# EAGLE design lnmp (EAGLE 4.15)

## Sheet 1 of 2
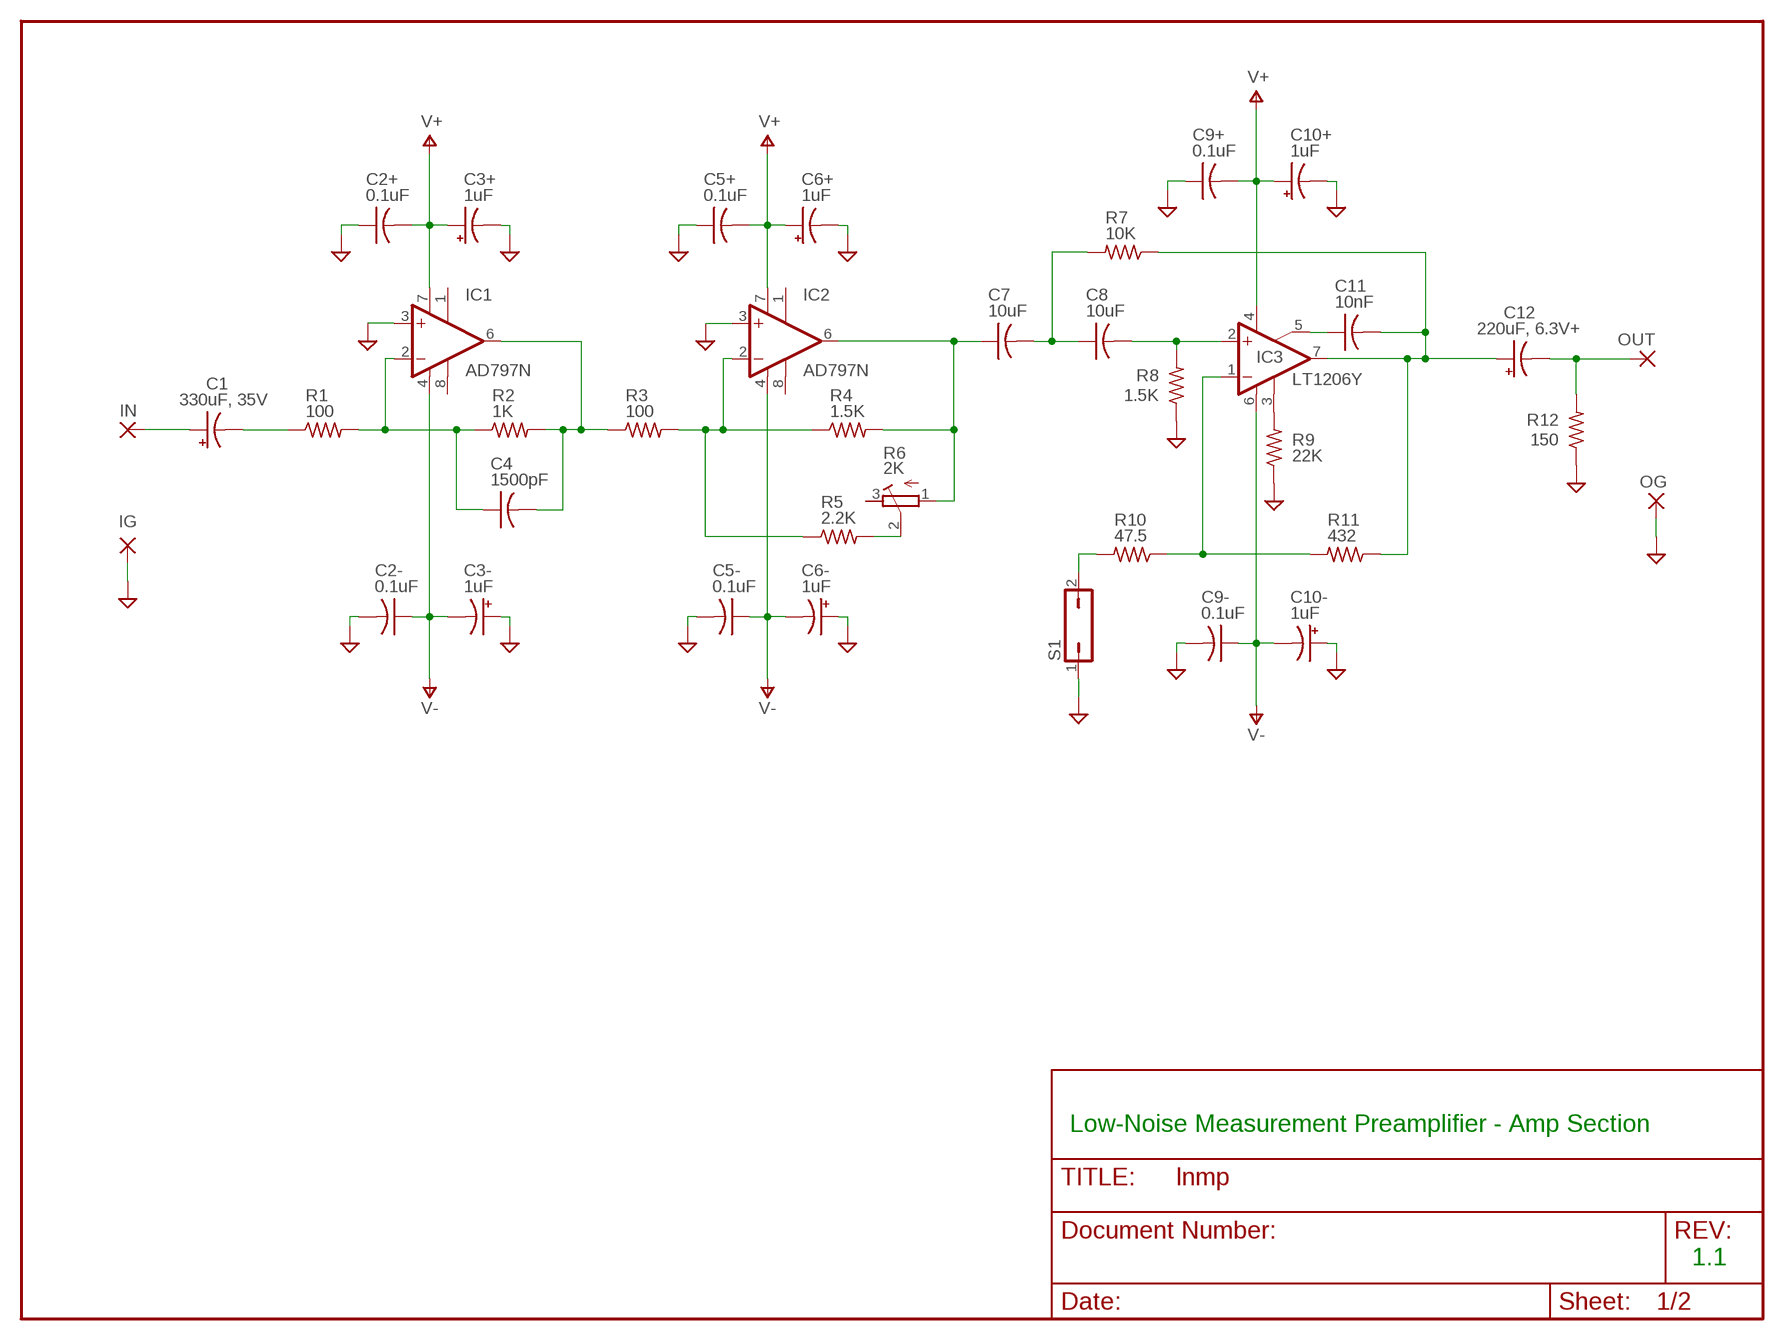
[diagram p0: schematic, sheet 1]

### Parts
C1  330uF, 35V  CPOL-USE5-10.5  [E5-10,5]
C2+  0.1uF  C-US050-025X075  [C050-025X075]
C2-  0.1uF  C-US050-025X075  [C050-025X075]
C3+  1uF  CPOL-USE2-4  [E2-4]
C3-  1uF  CPOL-USE2-4  [E2-4]
C4  1500pF  C-US050-025X075  [C050-025X075]
C5+  0.1uF  C-US050-025X075  [C050-025X075]
C5-  0.1uF  C-US050-025X075  [C050-025X075]
C6+  1uF  CPOL-USE2-4  [E2-4]
C6-  1uF  CPOL-USE2-4  [E2-4]
C7  10uF  C-US050-075X075  [C050-075X075]
C8  10uF  C-US050-075X075  [C050-075X075]
C9+  0.1uF  C-US050-025X075  [C050-025X075]
C9-  0.1uF  C-US050-025X075  [C050-025X075]
C10+  1uF  CPOL-USE2-4  [E2-4]
C10-  1uF  CPOL-USE2-4  [E2-4]
C11  10nF  C-US050-025X075  [C050-025X075]
C12  220uF, 6.3V+  CPOL-USE3.5-8  [E3,5-8]
IC1  AD797N  OPA132P  [DIL08]
IC2  AD797N  OPA132P  [DIL08]
IC3  LT1206Y  [TO-220-7]
IG  2,15/1,0  [2,15/1,0]
IN  2,15/1,0  [2,15/1,0]
OG  2,15/1,0  [2,15/1,0]
OUT  2,15/1,0  [2,15/1,0]
R1  100  R-US_0207/10  [0207/10]
R2  1K  R-US_0207/10  [0207/10]
R3  100  R-US_0207/10  [0207/10]
R4  1.5K  R-US_0207/10  [0207/10]
R5  2.2K  R-US_0207/10  [0207/10]
R6  2K  R-TRIMM3296W  [RTRIM3296W]
R7  10K  R-US_0207/10  [0207/10]
R8  1.5K  R-US_0207/10  [0207/10]
R9  22K  R-US_0207/10  [0207/10]
R10  47.5  R-US_0207/10  [0207/10]
R11  432  R-US_0207/10  [0207/10]
R12  150  R-US_0207/10  [0207/10]
S1  JP1Q  [JP1]

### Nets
GND1: C2+.1 C2-.2 C3+.- C3-.+ C5+.1 C5-.2 C6+.- C6-.+ C9+.1 C9-.2 C10+.- C10-.+ IC1.3(+IN) IC2.3(+IN) IG.1(P) OG.1(P) R8.1 R9.1 R12.1 S1.1 ; also sheet 2
N$1: C7.2 C8.1 R7.2
N$2: C8.2 IC3.2(+IN) R8.2
N$3: C4.1 IC1.2(-IN) R1.2 R2.1
N$5: C1.+ IN.1(P)
N$7: C11.2 C12.+ IC3.7(OUT) R7.1 R11.1
N$8: C4.2 IC1.6(OUT) R2.2 R3.1
N$9: C1.- R1.1
N$11: R5.2 R6.2(S)
N$12: IC2.2(-IN) R3.2 R4.1 R5.1
N$13: IC3.1(-IN) R10.1 R11.2
N$14: C7.1 IC2.6(OUT) R4.2 R6.1(E)
N$15: IC3.3(SD) R9.2
N$16: C11.1 IC3.5(COMP)
N$17: R10.2 S1.2
OUT: C12.- OUT.1(P) R12.2
V+: C2+.2 C3+.+ C5+.2 C6+.+ C9+.2 C10+.+ IC1.7(V+) IC2.7(V+) IC3.4(V+) ; also sheet 2
V-: C2-.1 C3-.- C5-.1 C6-.- C9-.1 C10-.- IC1.4(V-) IC2.4(V-) IC3.6(V-) ; also sheet 2
Unconnected: IC1.1(TRIM1) IC1.8(TRIM2) IC2.1(TRIM1) IC2.8(TRIM2) R6.3(A)

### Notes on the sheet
- Low-Noise Measurement Preamplifier - Amp Section
- 1.1

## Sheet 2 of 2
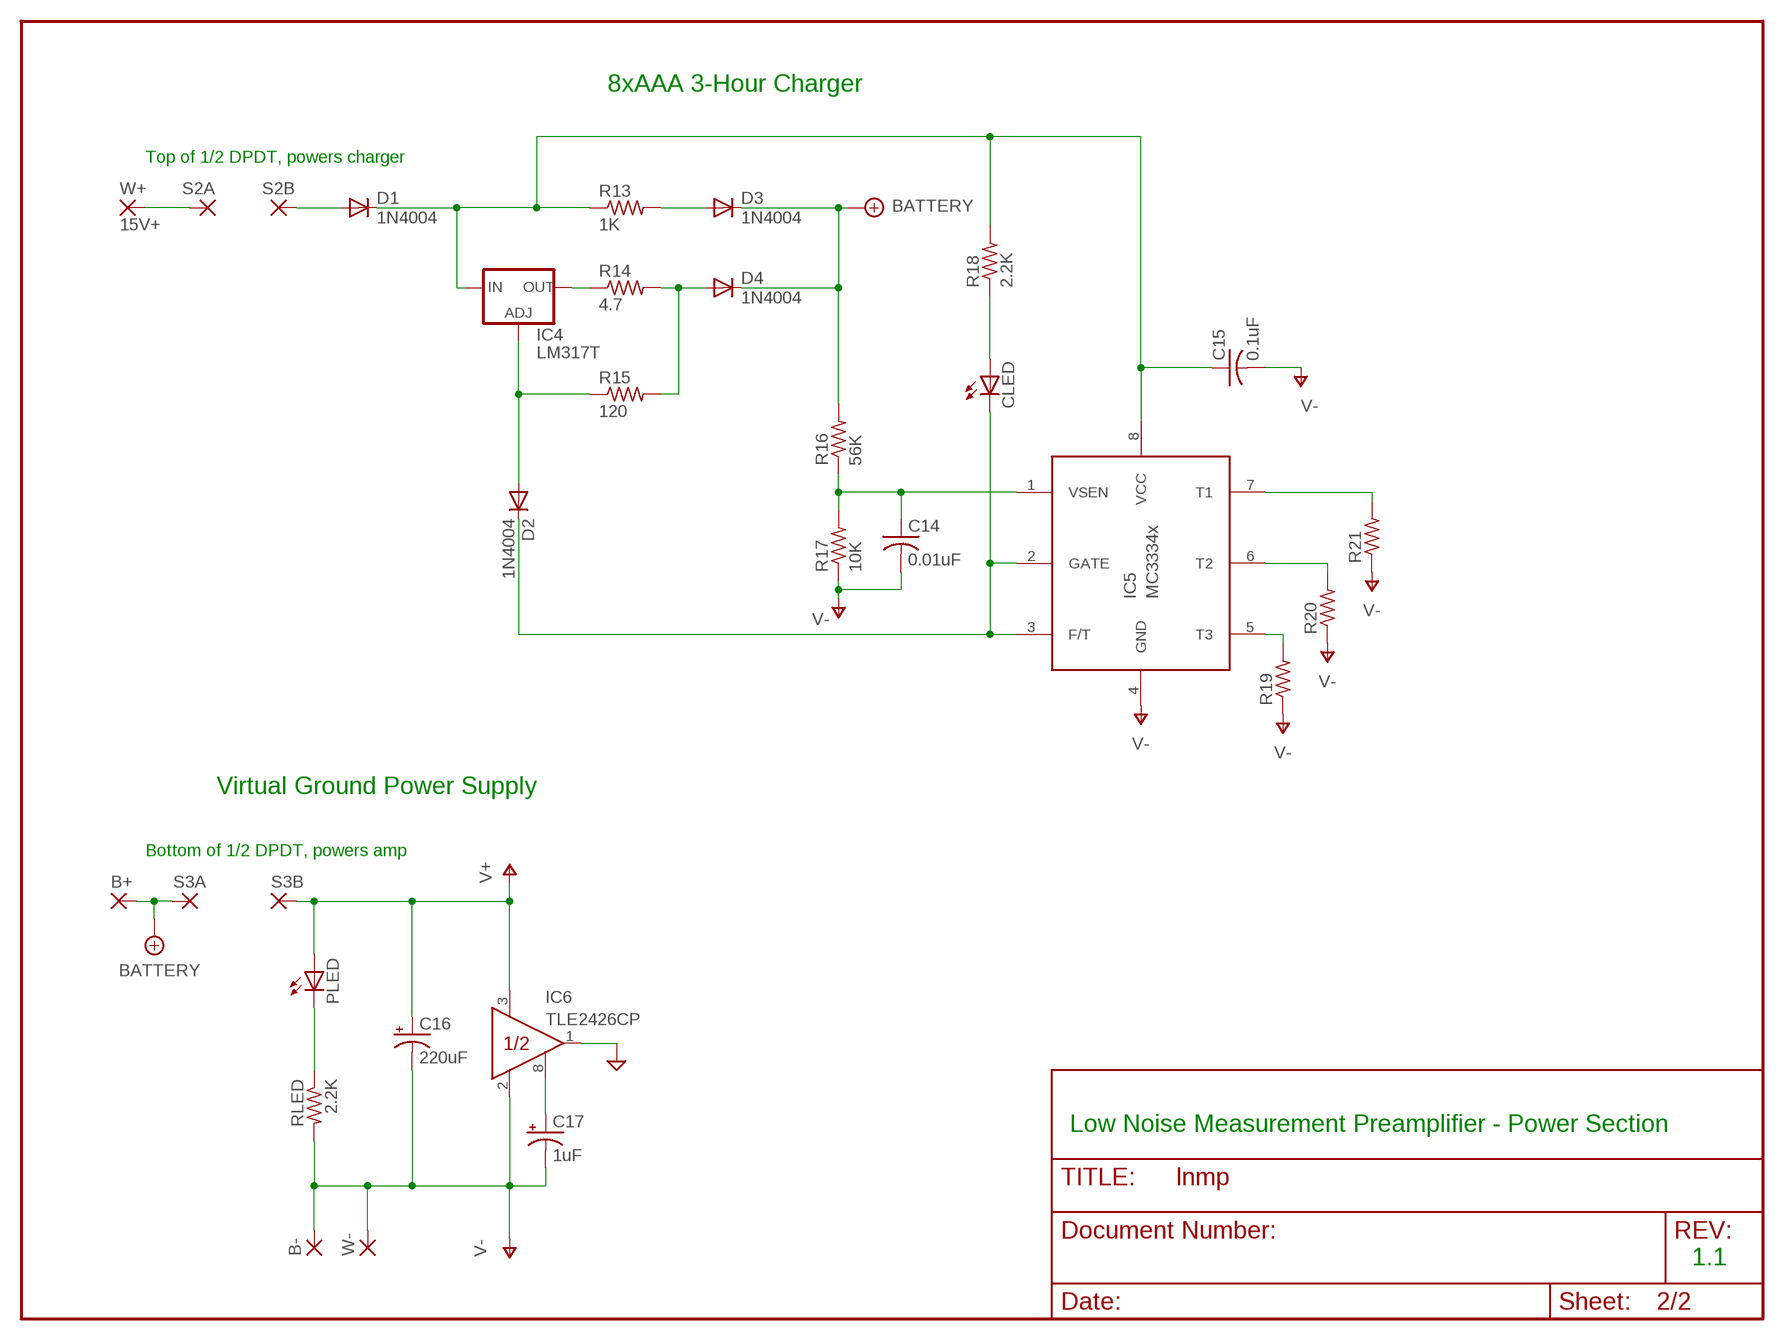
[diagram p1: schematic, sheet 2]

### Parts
B+  2,54/1,0  [2,54/1,0]
B-  2,15/1,0  [2,15/1,0]
C14  0.01uF  C-US050-025X075  [C050-025X075]
C15  0.1uF  C-US050-025X075  [C050-025X075]
C16  220uF  CPOL-USE5-10.5  [E5-10,5]
C17  1uF  CPOL-USE2-4  [E2-4]
CLED  LED3MM  [LED3MM]
D1  1N4004  [DO41-10]
D2  1N4004  [DO41-10]
D3  1N4004  [DO41-10]
D4  1N4004  [DO41-10]
IC4  LM317T  LM317TS  [317TS]
IC5  MC3334x  MC3334XP  [DIP-8]
IC6  TLE2426CP  [DIP-8]
PLED  LED3MM  [LED3MM]
R13  1K  R-US_0207/10  [0207/10]
R14  4.7  R-US_0411/15  [0411/15]
R15  120  R-US_0207/10  [0207/10]
R16  56K  R-US_0207/10  [0207/10]
R17  10K  R-US_0207/10  [0207/10]
R18  2.2K  R-US_0207/10  [0207/10]
R19  R-US_0207/10  [0207/10]
R20  R-US_0207/10  [0207/10]
R21  R-US_0207/10  [0207/10]
RLED  2.2K  R-US_0207/10  [0207/10]
S2A  2,54/1,0  [2,54/1,0]
S2B  2,54/1,0  [2,54/1,0]
S3A  2,54/1,0  [2,54/1,0]
S3B  2,54/1,0  [2,54/1,0]
W+  15V+  2,54/1,0  [2,54/1,0]
W-  2,54/1,0  [2,54/1,0]

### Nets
+10V: B+.1(P) D3.C D4.C R16.2 S3A.1(P) ; supply symbol labelled BATTERY
GND1: IC6.1(OUT) ; also sheet 1
N$4: C17.+ IC6.8(NR)
N$6: PLED.K(C) RLED.1
N$19: S2A.1(P) W+.1(P)
N$20: D1.A S2B.1(P)
N$22: IC4.2(OUT) R14.1
N$23: D4.A R14.2 R15.2
N$24: CLED.A R18.1
N$25: D2.A IC4.1(ADJ) R15.1
N$26: CLED.K(C) D2.C IC5.2(GATE) IC5.3(F/T)
N$27: C14.1 IC5.1(VSEN) R16.1 R17.2
N$28: C15.1 D1.C IC4.3(IN) IC5.8(VCC) R13.1 R18.2
N$29: IC5.5(T3) R19.2
N$30: D3.A R13.2
N$32: IC5.6(T2) R20.2
N$33: IC5.7(T1) R21.2
V+: C16.+ IC6.3(IN) PLED.A S3B.1(P) ; also sheet 1
V-: B-.1(P) C14.2 C15.2 C16.- C17.- IC5.4(GND) IC6.2(COM) R17.1 R19.1 R20.1 R21.1 RLED.2 W-.1(P) ; also sheet 1

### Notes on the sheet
- 8xAAA 3-Hour Charger
- Top of 1/2 DPDT, powers charger
- Virtual Ground Power Supply
- Bottom of 1/2 DPDT, powers amp
- Low Noise Measurement Preamplifier - Power Section
- 1.1

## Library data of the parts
B+ S2A S2B S3A S3B W+ W- = wirepad:2,54/1,0: THROUGH-HOLE PAD
B- IG IN OG OUT = wirepad:2,15/1,0: THROUGH-HOLE PAD
C1 C3+ C3- C6+ C6- C10+ C10- C12 C16 C17 = rcl:CPOL-US: POLARIZED CAPACITOR, American symbol
C2+ C2- C4 C5+ C5- C7 C8 C9+ C9- C11 C14 C15 = rcl:C-US: CAPACITOR, American symbol
CLED PLED = led:LED: LED
D1-D4 = diode:1N4004: DIODE
IC1 IC2 = burr-brown:OPA132: Operational Amplifiers High Speed FET-Input
IC3 = opamps:LT1206: Linear Technology LT1206 CFB op-amp with shutdown
IC4 = v-reg:LM317TS: VOLTAGE REGULATOR
IC5 = power-mgmt:MC3334X: Motorola MC3334x NiMH/NiCd fast charge controller
IC6 = tle2426:TLE2426*: Texas Instruments "rail splitter" with noise-reduction
R1-R5 R7-R21 RLED = rcl:R-US_: RESISTOR, American symbol
R6 = rcl:R-TRIMM: Trimm resistor
S1 = jumper:JP1Q: JUMPER

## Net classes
0 default: width 0.61 mm

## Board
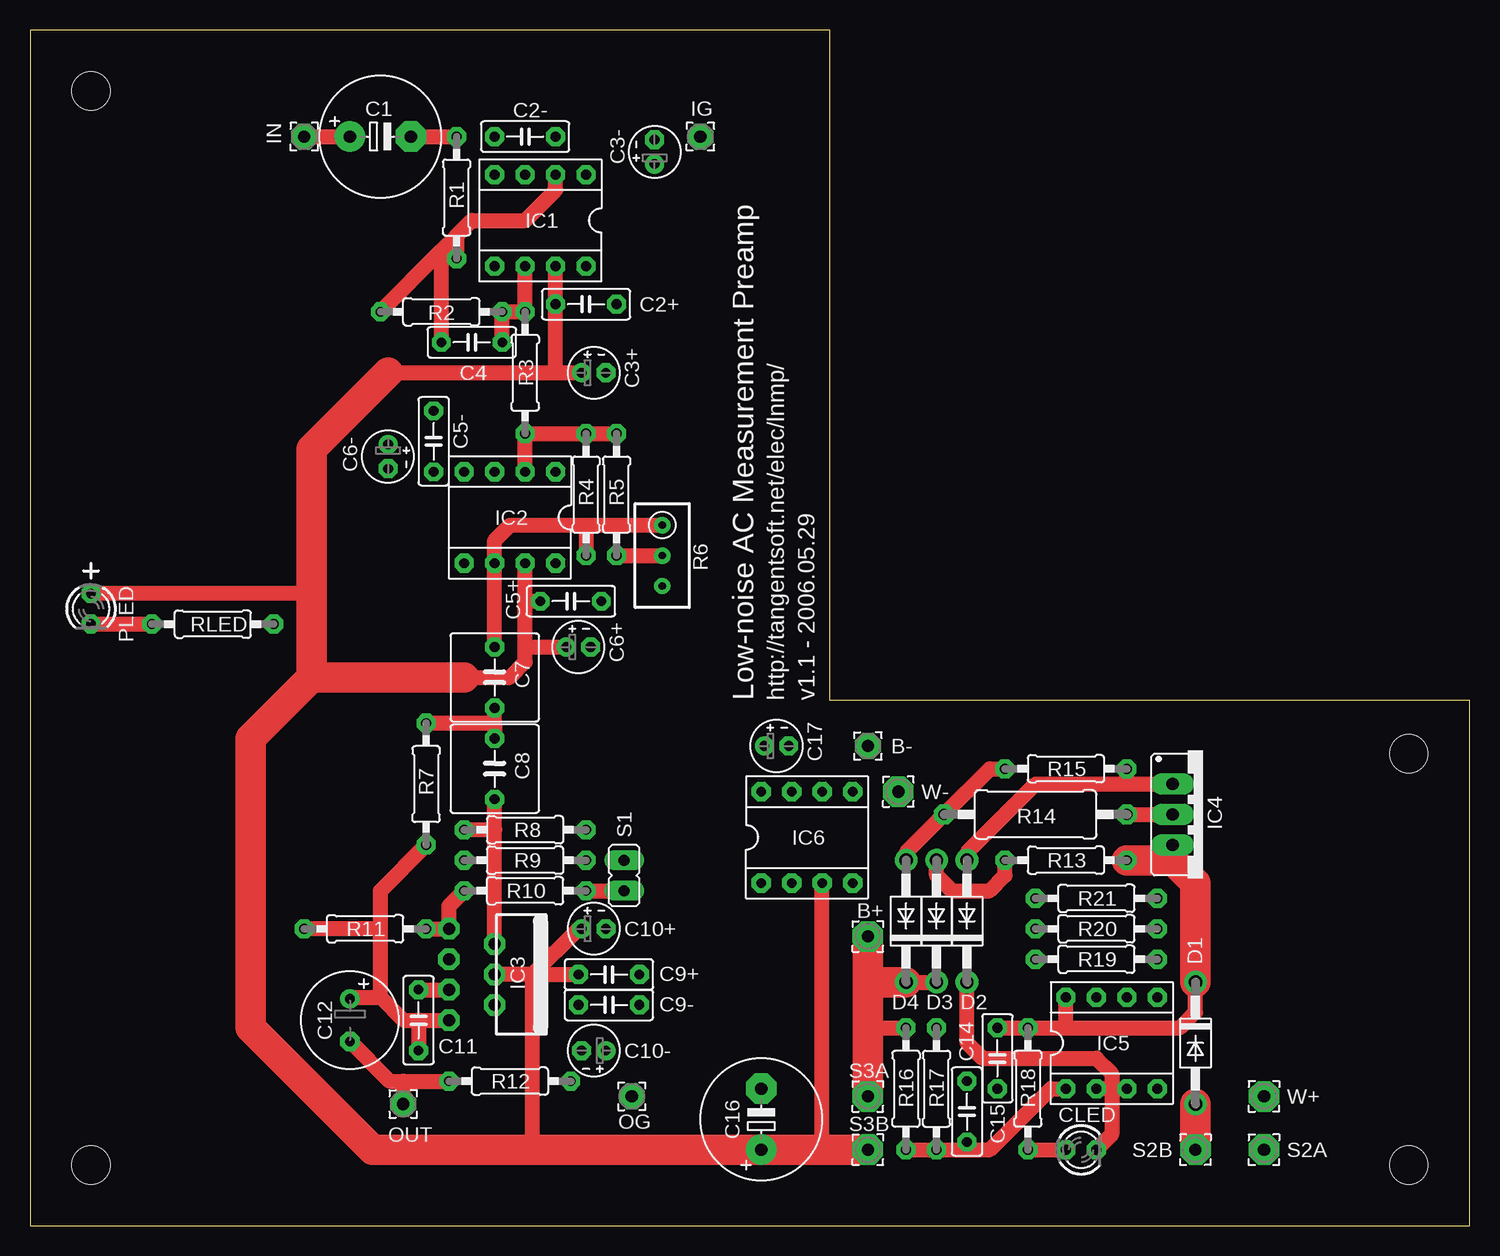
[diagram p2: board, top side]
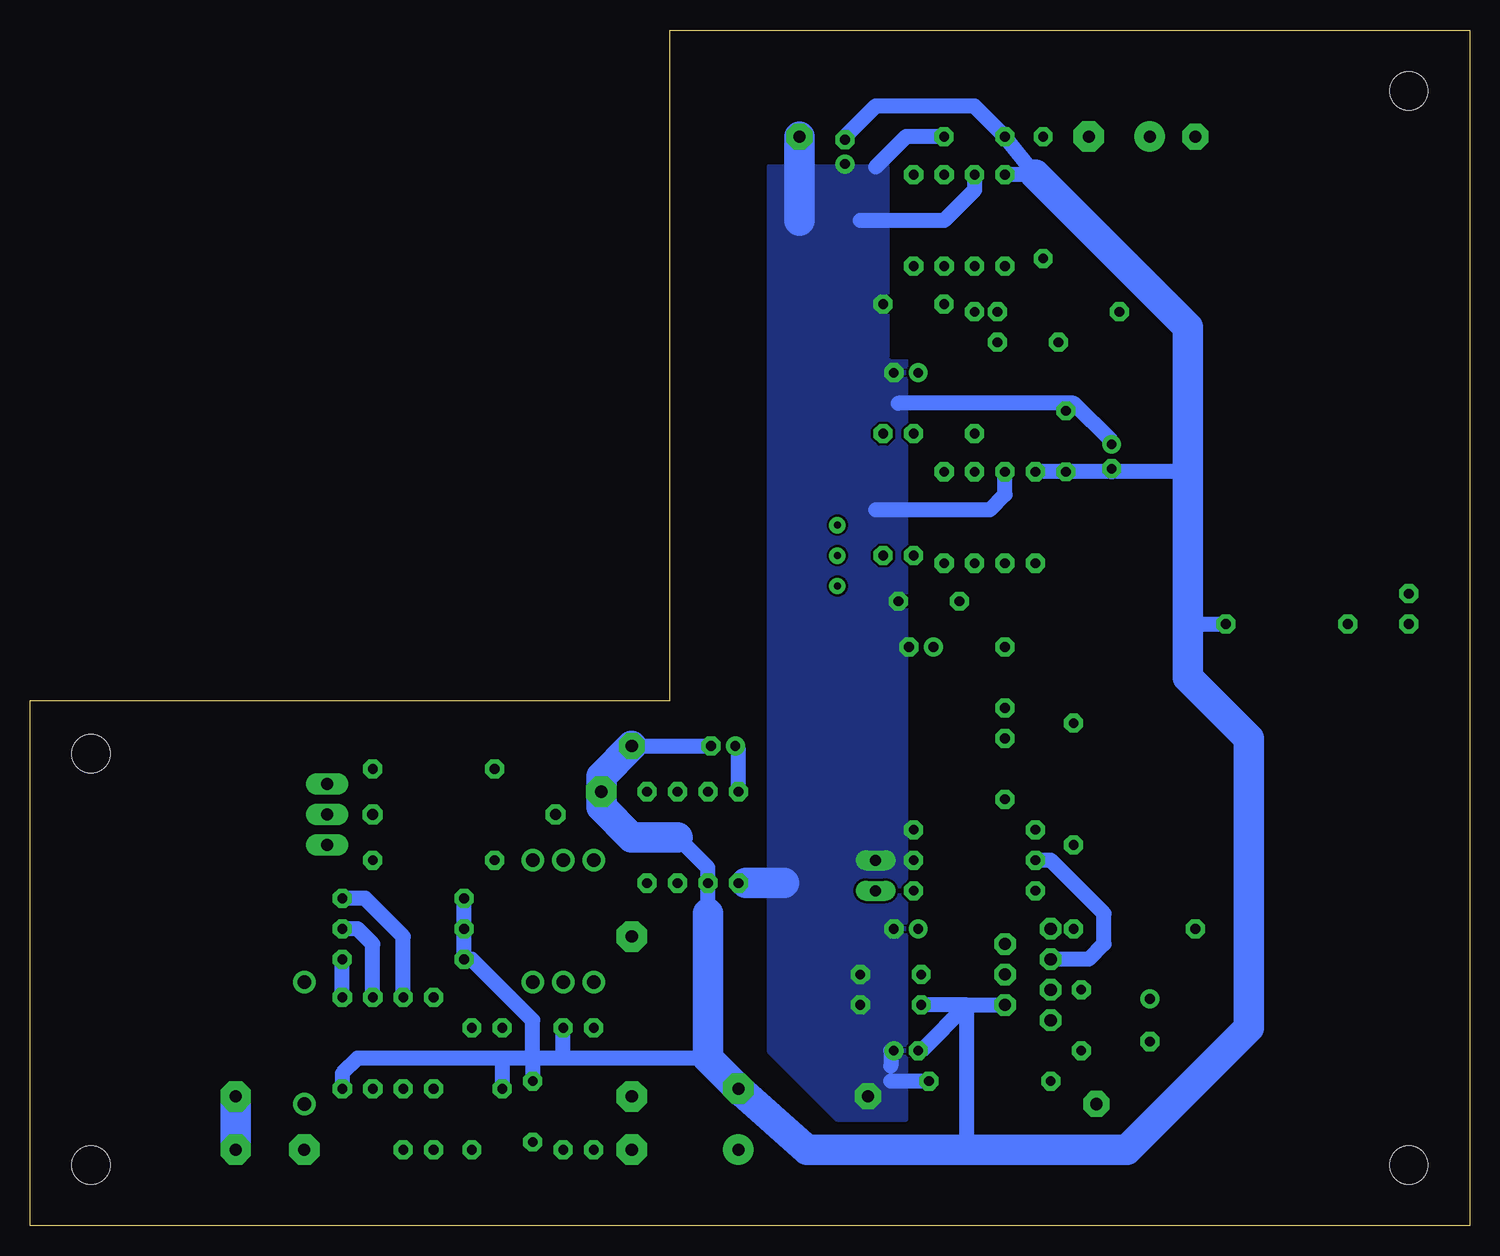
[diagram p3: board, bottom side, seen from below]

Size 120.02 x 99.69 mm. Coordinates in mm from the lower left corner, seen from the top.
Outline: 0,0 120.02,0 120.02,43.81 66.67,43.81 66.67,99.69 0,99.69 0,0
Copper layers (1*16): Top 0.035mm / dielectric 1.5mm / Bottom 0.035mm
Design rules "local": minimum track width 10mil, minimum drill 10mil, track to track 8mil, track to pad 20mil, pad to pad 8mil, via to via 8mil, smd to smd 8mil, copper to edge 40mil, drill to drill 8mil, minimum pad ring 15mil, minimum via ring 8mil, stop-mask expansion 4mil, vias tented up to drill 0mil, thermal gap 0mil
Holes 3.17 mm at 5.08,94.61 5.08,5.08 114.94,5.08 114.94,39.37
bRestrict: area 45.1,72.4 to 48.3,88.3

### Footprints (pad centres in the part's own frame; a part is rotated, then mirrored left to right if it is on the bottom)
2,54/1,0 = drill 1.016 pad 2.54 octagon: 1 0,0
2,15/1,0 = drill 1.016 pad 2.159 octagon: 1 0,0
E5-10,5 = drill 1.016 pad 2.54 round: + -2.54,0 | drill 1.016 pad 2.54 octagon: - 2.54,0
C050-025X075 = drill 0.813 octagon: 1 -2.54,0; 2 2.54,0
E2-4 = drill 0.813 pad 1.27 round: + -1.016,0 | drill 0.813 pad 1.27 octagon: - 1.016,0
C050-075X075 = drill 0.813 octagon: 1 -2.54,0; 2 2.54,0
E3,5-8 = drill 0.813 pad 1.6 round: + -1.778,0 | drill 0.813 pad 1.6 octagon: - 1.778,0
LED3MM = drill 0.813 octagon: A -1.27,0; K 1.27,0
DO41-10 = drill 1.118 round: A 5.08,0; C -5.08,0
DIL08 = drill 0.813 pad 1.6 octagon: 1 -3.81,-3.81; 2 -1.27,-3.81; 3 1.27,-3.81; 4 3.81,-3.81; 5 3.81,3.81; 6 1.27,3.81; 7 -1.27,3.81; 8 -3.81,3.81
TO-220-7 = drill 1.016 octagon: 1 -3.81,3.81; 2 0,2.54; 3 -3.81,1.27; 4 0,0; 5 -3.81,-1.27; 6 0,-2.54; 7 -3.81,-3.81
317TS = drill 1.016 long: 1 -2.54,-2.54; 2 0,-2.54; 3 2.54,-2.54
DIP-8 = drill 0.813 pad 1.6 octagon: 1 -3.81,-3.81; 2 -1.27,-3.81; 3 1.27,-3.81; 4 3.81,-3.81; 5 3.81,3.81; 6 1.27,3.81; 7 -1.27,3.81; 8 -3.81,3.81
DIP-8' = drill 0.813 pad 1.6 octagon: 1 -3.81,3.81; 2 -3.81,1.27; 3 -3.81,-1.27; 4 -3.81,-3.81; 5 3.81,-3.81; 6 3.81,-1.27; 7 3.81,1.27; 8 3.81,3.81
0207/10 = drill 0.813 octagon: 1 -5.08,0; 2 5.08,0
RTRIM3296W = drill 0.61 round: 1 0,-2.54; 2 0,0; 3 0,2.54
0411/15 = drill 0.914 octagon: 1 -7.62,0; 2 7.62,0
JP1 = drill 0.914 long: 1 0,-1.27; 2 0,1.27

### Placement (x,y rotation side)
B+  69.85,24.13 0 top
B-  69.85,40.01 180 top
C1  29.21,90.81 0 top
C2+  46.35,76.83 180 top
C2-  41.27,90.81 0 top
C3+  46.99,71.12 0 top
C3-  52.07,89.53 90 top
C4  36.83,73.66 0 top
C5+  45.09,52.07 180 top
C5-  33.66,65.41 90 top
C6+  45.72,48.26 0 top
C6-  29.84,64.14 270 top
C7  38.73,45.72 270 top
C8  38.73,38.1 270 top
C9+  48.26,20.95 180 top
C9-  48.26,18.41 0 top
C10+  46.99,24.77 0 top
C10-  46.99,14.61 180 top
C11  32.38,17.14 270 top
C12  26.67,17.14 270 top
C14  78.11,9.53 90 top
C15  80.64,13.97 270 top
C16  60.96,8.89 90 top
C17  62.23,40.01 0 top
CLED  87.63,6.35 0 top
D1  97.16,15.24 270 top
D2  78.11,25.4 90 top
D3  75.56,25.4 90 top
D4  73.03,25.4 90 top
IC1  42.55,83.82 180 top
IC2  40.01,59.05 180 top
IC3  38.73,20.95 0 top
IC4  97.79,34.29 270 top
IC5  90.17,15.24 0 top
IC6  TLE2426CP  [DIP-8']  64.77,32.38 90 top
IG  55.88,90.81 270 top
IN  22.86,90.81 270 top
OG  50.16,10.79 0 top
OUT  31.11,10.16 180 top
PLED  5.08,51.44 270 top
R1  35.56,85.72 270 top
R2  34.29,76.2 0 top
R3  41.27,71.12 270 top
R4  46.35,60.96 270 top
R5  48.9,60.96 270 top
R6  52.7,55.88 180 top
R7  33.02,36.83 90 top
R8  41.27,33.02 180 top
R9  41.27,30.48 180 top
R10  41.27,27.94 0 top
R11  27.94,24.77 0 top
R12  40.01,12.06 180 top
R13  86.36,30.48 180 top
R14  83.82,34.29 180 top
R15  86.36,38.1 180 top
R16  73.03,11.43 90 top
R17  75.56,11.43 270 top
R18  83.19,11.43 90 top
R19  88.9,22.23 0 top
R20  88.9,24.77 0 top
R21  88.9,27.3 0 top
RLED  15.24,50.16 0 top
S1  49.53,29.21 180 top
S2A  102.87,6.35 0 top
S2B  97.16,6.35 180 top
S3A  69.85,10.79 0 top
S3B  69.85,6.35 0 top
W+  102.87,10.79 180 top
W-  72.39,36.2 90 top

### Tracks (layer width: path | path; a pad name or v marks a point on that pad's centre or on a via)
+10V
  Top 1.27: 69.85,16.51 R16.2 | D4.C D3.C
  Top 2.54: D4.C 69.85,20.32 B+.1 69.85,16.51 S3A.1
GND1
  Bottom 1.27: 60.33,28.57 IC6.1 | C2-.2 46.99,90.81 49.53,88.27 | C6-.+ 29.84,65.41 33.02,68.58 33.66,68.58 | 33.66,68.58 C5-.2 | 33.66,68.58 47.62,68.58 | IC1.3 41.27,86.36 43.81,83.82 50.8,83.82 | IC2.3 38.73,60.96 40.01,59.69 49.53,59.69 | C10-.+ 48.26,14.61 48.26,13.34 | R12.1 48.26,12.06
  Bottom 2.54: 57.15,28.57 60.33,28.57 | 55.88,83.82 IG.1
  pour Bottom: 58.42,88.27 58.42,14.61 52.7,8.89 46.99,8.89 46.99,88.27
N$1
  Top 1.27: R7.2 38.73,41.91 | 38.73,41.91 C7.2 | 38.73,41.91 C8.1
N$2
  Top 1.27: IC3.2 38.73,33.02 | 38.73,33.02 C8.2 | 38.73,33.02 R8.2
N$3
  Top 1.27: R2.1 34.29,81.28 | 34.29,81.28 35.56,82.55 | 35.56,82.55 36.83,83.82 41.27,83.82 43.81,86.36 IC1.2 | 35.56,82.55 R1.2 | 34.29,81.28 C4.1
N$4
  Bottom 1.27: C17.+ 60.96,39.75 IC6.8
N$5
  Top 1.27: IN.1 C1.+
N$6
  Top 1.27: PLED.K RLED.1
N$7
  Top 1.27: R7.1 29.21,27.94 29.21,24.77 | 29.21,19.05 29.21,24.77 | 29.21,19.05 31.11,17.14 32.38,17.14 | 32.38,17.14 IC3.7 | C12.+ 26.8,19.05 29.21,19.05 | 29.21,24.77 R11.1 | 32.38,17.14 C11.2
N$8
  Top 1.27: IC1.6 R3.1 R2.2 C4.2
N$9
  Top 1.27: C1.- R1.1
N$11
  Top 1.27: R5.2 R6.2
N$12
  Top 1.27: R5.1 R4.1 R3.2 IC2.2
N$13
  Top 1.27: R11.2 IC3.1 34.92,26.67 R10.1
N$14
  Top 1.27: 46.35,58.42 40.01,58.42 38.73,57.15 IC2.6 C7.1 | 46.35,58.42 R4.2 | 46.35,58.42 R6.1
N$15
  Bottom 1.27: R9.2 34.92,30.48 30.48,26.04 30.48,23.5 31.75,22.23 IC3.3
N$16
  Top 1.27: C11.1 IC3.5
N$17
  Top 1.27: R10.2 S1.2
N$19
  Bottom 2.54: S2A.1 W+.1
N$20
  Top 2.54: S2B.1 D1.A
N$22
  Top 1.27: R14.1 IC4.2
N$23
  Top 1.27: R15.2 80.01,38.1 R14.2 73.03,31.11 D4.A
N$24
  Top 1.27: R18.1 CLED.A
N$25
  Top 1.27: 91.44,36.83 83.82,36.83 78.11,31.11 D2.A | 91.44,36.83 IC4.1 | 91.44,36.83 R15.1
N$26
  Top 1.27: 90.17,11.43 IC5.2 | 90.17,11.43 IC5.3 | 90.17,11.43 90.17,12.7 88.9,13.97 79.38,13.97 78.11,15.24 D2.C | CLED.K 90.17,7.62 90.17,11.43
N$27
  Top 1.27: IC5.1 85.09,11.43 80.01,6.35 78.11,6.35 | 78.11,6.35 R17.2 R16.1 | 78.11,6.35 C14.1
N$28
  Top 1.27: 86.36,16.51 95.89,16.51 97.16,17.78 D1.C | 86.36,16.51 IC5.8 | C15.1 R18.2 86.36,16.51 | 95.25,30.48 IC4.3
  Top 2.54: R13.1 95.25,30.48 97.16,28.57 D1.C
N$29
  Bottom 1.27: IC5.5 R19.2
N$30
  Top 1.27: R13.2 81.28,29.21 80.01,27.94 76.83,27.94 75.56,29.21 D3.A
N$32
  Bottom 1.27: R20.2 92.71,24.77 91.44,23.5 IC5.6
N$33
  Bottom 1.27: R21.2 92.08,27.3 88.9,24.13 IC5.7
OUT
  Top 1.27: C12.- 29.97,12.06 31.11,12.06 | 31.11,12.06 R12.2 | 31.11,12.06 OUT.1
V+
  Top 1.27: 41.91,20.95 C9+.2 | 41.91,20.95 IC3.4 | 41.91,6.35 41.91,20.95 | 41.91,20.95 45.72,24.77 C10+.+ | 23.5,52.7 PLED.A | 36.2,45.72 40.01,45.72 41.27,46.99 41.27,48.26 | 41.27,48.26 41.27,52.07 | 29.84,71.12 43.81,71.12 | 43.81,71.12 C3+.+ | 43.81,71.12 C2+.2 IC1.7 | 41.27,52.07 C5+.2 | 41.27,52.07 IC2.7 | 66.04,6.35 IC6.3 | 41.27,48.26 C6+.+
  Top 2.54: 23.5,45.72 18.41,40.64 18.41,16.51 28.57,6.35 41.91,6.35 C16.+ 66.04,6.35 S3B.1 | 23.5,45.72 23.5,52.7 23.5,64.77 29.84,71.12 | 23.5,45.72 36.2,45.72
V-
  Bottom 1.27: 63.5,26.04 IC6.2 63.5,29.84 66.04,32.38 | 41.91,18.41 C9-.1 | 41.91,18.41 IC3.6 | 41.91,6.35 41.91,18.41 | 41.91,18.41 45.72,14.61 C10-.- | C3-.- 52.07,90.81 49.53,93.34 41.27,93.34 C2-.1 36.2,87.63 IC1.4 | 23.5,62.87 29.84,62.87 | 29.84,62.87 C5-.1 IC2.4 | 29.84,62.87 C6-.- | 23.5,50.16 RLED.2 | R21.1 R20.1 R19.1 83.19,22.23 78.11,17.14 78.11,13.97 | IC5.4 93.98,12.7 92.71,13.97 80.64,13.97 | 63.5,13.97 75.56,13.97 | 78.11,13.97 80.64,13.97 | 78.11,13.97 C14.2 | 80.64,13.97 C15.2 | 75.56,13.97 R17.1 | 75.56,13.97 78.11,13.97 | B-.1 C17.-
  Bottom 2.54: 36.2,87.63 23.5,74.93 23.5,62.87 23.5,50.16 23.5,45.72 18.41,40.64 18.41,16.51 28.57,6.35 41.91,6.35 55.24,6.35 C16.- 63.5,13.97 63.5,26.04 | B-.1 72.39,37.47 W-.1 72.39,34.92 69.85,32.38 66.04,32.38

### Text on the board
tPlace: Low-noise AC Measurement Preamp | http://tangentsoft.net/elec/lnmp/ | v1.1 - 2006.05.29 | IC3
_tplace: C1 | IG | C2- | IN | C3- | R1 | IC1 | R2 | C2+ | C4 | R3 | C3+ | C5- | C6- | R4 | R5 | IC2 | R6 | PLED | C5+ | RLED | C6+ | C7 | Low-noise AC Measurement Preamp | http://tangentsoft.net/elec/lnmp/ | v1.1 - 2006.05.29 | C17 | B- | C8 | R15 | R7 | W- | R14 | IC4 | R8 | S1 | IC6 | R9 | R13 | R10 | R21 | B+ | R11 | C10+ | R20 | R19 | D1 | IC3 | C9+ | D4 | D3 | D2 | C9- | C12 | IC5 | C11 | C10- | C14 | S3A | R12 | R16 | R17 | C15 | R18 | W+ | CLED | OG | S3B | OUT | C16 | S2B | S2A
